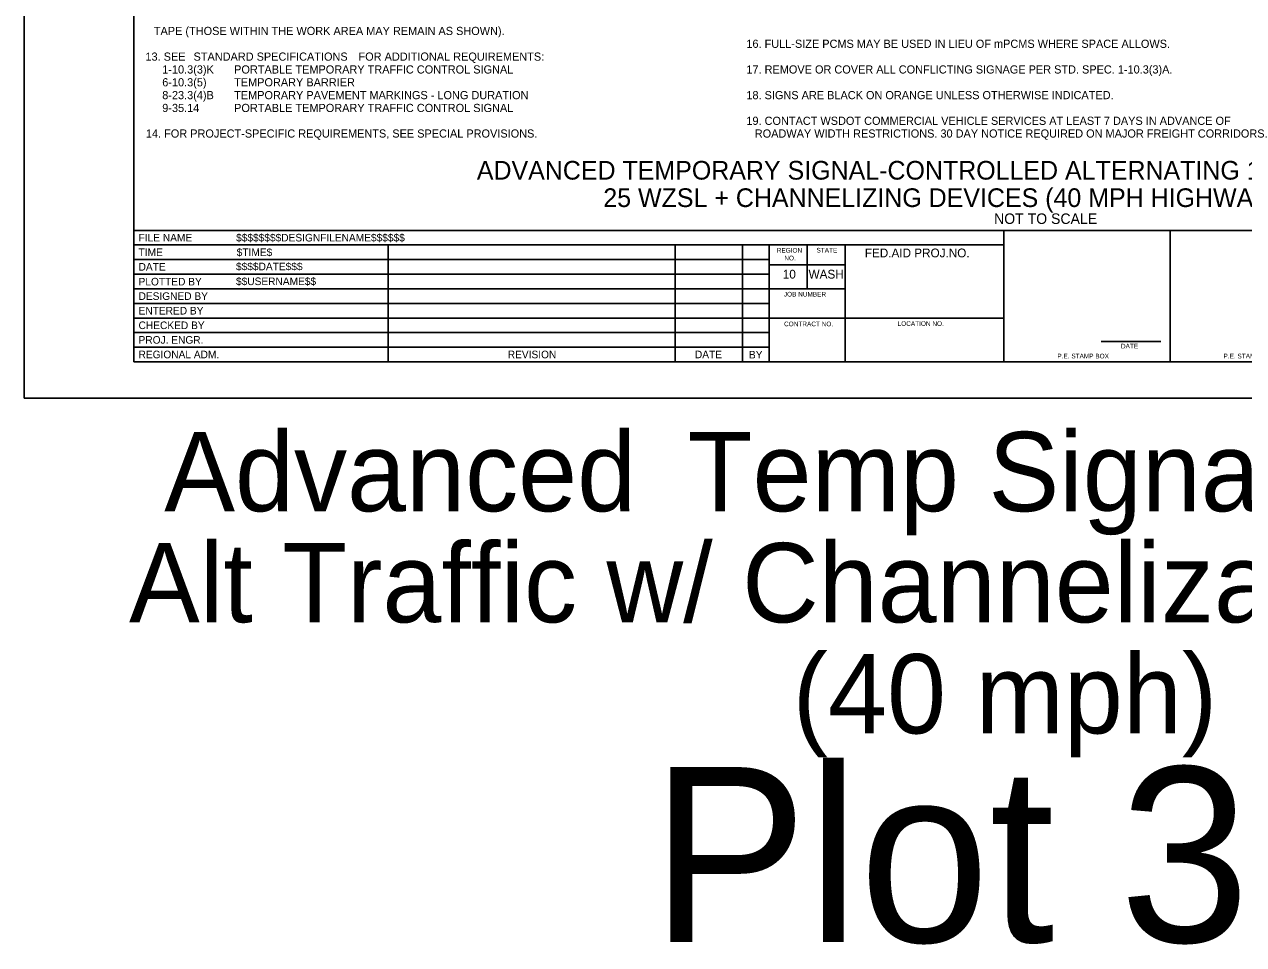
# Model space of a CAD drawing. Extents: x 99982 to 100176, y 99905 to 100011.
# Drawn here: x 100059.06 to 100069.51, y 99905.01 to 99912.89 of the extents above; entities that cross this region are included whole.
import ezdxf

# ---------------------------------------------------------------- set-up
doc = ezdxf.new("R2010")
doc.units = 0
for name, color, linetype in [('SH_DE_DetailHeading1Text', 7, 'Continuous'), ('SH_GI_GeneralNotesBodyText', 7, 'Continuous'), ('SH_GI_PlotLimits', 7, 'Continuous'), ('SH_GI_SheetBorder', 7, 'Continuous'), ('SH_GI_SheetLocationText', 7, 'Continuous'), ('SH_GI_SheetTextInCells', 7, 'Continuous'), ('SH_GI_TitleBlockText', 7, 'Continuous')]:
    doc.layers.add(name, color=color, linetype=linetype)

msp = doc.modelspace()

# ---------------------------------------------------------------- linework, layer by layer
at = {"layer": 'SH_GI_PlotLimits'}
msp.add_lwpolyline([(100059.062, 99909.687), (100076.062, 99909.687), (100076.062, 99920.687), (100059.062, 99920.687)], close=True, dxfattribs=at)
at = {"layer": 'SH_GI_SheetBorder'}
for p, q in [((100060, 99920.375), (100060, 99910)), ((100060, 99911.126), (100075.75, 99911.126)), ((100067.457, 99910), (100067.457, 99911.126)), ((100068.883, 99910), (100068.883, 99911.126)), ((100060, 99911.001), (100067.457, 99911.001)), ((100062.179, 99911.001), (100062.179, 99910)), ((100064.641, 99911.001), (100064.641, 99910)), ((100065.216, 99911.001), (100065.216, 99910)), ((100065.445, 99911.001), (100065.445, 99910)), ((100065.772, 99910.625), (100065.772, 99911.001)), ((100066.096, 99910), (100066.096, 99911.001)), ((100060, 99910.876), (100062.182, 99910.876)), ((100062.182, 99910.876), (100065.447, 99910.876)), ((100066.096, 99910.831), (100065.447, 99910.831)), ((100060, 99910.751), (100062.182, 99910.751)), ((100062.182, 99910.751), (100065.447, 99910.751)), ((100060, 99910.625), (100065.447, 99910.625)), ((100066.096, 99910.625), (100065.447, 99910.625)), ((100060, 99910.5), (100065.447, 99910.5)), ((100060, 99910.375), (100065.447, 99910.375)), ((100067.457, 99910.375), (100065.447, 99910.375)), ((100060, 99910.25), (100065.447, 99910.25)), ((100060, 99910.125), (100065.447, 99910.125)), ((100068.29, 99910.173), (100068.802, 99910.173)), ((100060, 99910), (100075.75, 99910))]:
    msp.add_line(p, q, dxfattribs=at)

# ---------------------------------------------------------------- texts
at = {"layer": 'SH_DE_DetailHeading1Text'}
for s, height, p in [('ADVANCED TEMPORARY SIGNAL-CONTROLLED ALTERNATING 1-LANE, 2-WAY TRAFFIC', 0.16, (100062.94, 99911.561)), ('25 WZSL + CHANNELIZING DEVICES (40 MPH HIGHWAYS, 8+ DAYS)', 0.16, (100064.024, 99911.326)), ('NOT TO SCALE', 0.09, (100067.373, 99911.181))]:
    msp.add_text(s, height=height, rotation=360, dxfattribs=at).set_placement(p)
at = {"layer": 'SH_GI_GeneralNotesBodyText'}
for s, p in [('TAPE (THOSE WITHIN THE WORK AREA MAY REMAIN AS SHOWN).', (100060.172, 99912.8)), ('16. FULL-SIZE PCMS MAY BE USED IN LIEU OF mPCMS WHERE SPACE ALLOWS.', (100065.25, 99912.69)), ('13. SEE ', (100060.1, 99912.58)), ('STANDARD SPECIFICATIONS', (100060.512, 99912.58)), (' FOR ADDITIONAL REQUIREMENTS:', (100061.9, 99912.58)), ('1-10.3(3)K', (100060.244, 99912.47)), ('PORTABLE TEMPORARY TRAFFIC CONTROL SIGNAL', (100060.86, 99912.47)), ('17. REMOVE OR COVER ALL CONFLICTING SIGNAGE PER STD. SPEC. 1-10.3(3)A. ', (100065.25, 99912.47)), ('6-10.3(5)', (100060.244, 99912.36)), ('TEMPORARY BARRIER', (100060.86, 99912.36)), ('8-23.3(4)B', (100060.244, 99912.25)), ('TEMPORARY PAVEMENT MARKINGS - LONG DURATION', (100060.86, 99912.25)), ('18. SIGNS ARE BLACK ON ORANGE UNLESS OTHERWISE INDICATED.', (100065.25, 99912.25)), ('9-35.14', (100060.244, 99912.14)), ('PORTABLE TEMPORARY TRAFFIC CONTROL SIGNAL', (100060.86, 99912.14)), ('19. CONTACT WSDOT COMMERCIAL VEHICLE SERVICES AT LEAST 7 DAYS IN ADVANCE OF ', (100065.25, 99912.03)), ('14. FOR PROJECT-SPECIFIC REQUIREMENTS, SEE SPECIAL PROVISIONS.', (100060.104, 99911.921)), ('ROADWAY WIDTH RESTRICTIONS. 30 DAY NOTICE REQUIRED ON MAJOR FREIGHT CORRIDORS.', (100065.322, 99911.921))]:
    msp.add_text(s, height=0.07, rotation=360, dxfattribs=at).set_placement(p)
at = {"layer": 'SH_GI_SheetLocationText'}
for s, height, p in [('Advanced', 0.68, (100060.261, 99908.719)), (' Temp Signal-Controlled', 0.68, (100064.495, 99908.719)), ('Alt Traffic w/ Channelization Devices', 0.68, (100059.959, 99907.767)), (' (40 mph)', 0.68, (100065.394, 99906.815)), ('Plot 34', 1.5, (100064.434, 99905.027))]:
    msp.add_text(s, height=height, dxfattribs=at).set_placement(p)
at = {"layer": 'SH_GI_SheetTextInCells'}
for s, height, p in [('FILE NAME', 0.0651, (100060.041, 99911.031)), ('TIME', 0.0651, (100060.041, 99910.906)), ('REGION', 0.04, (100065.51, 99910.935)), ('STATE', 0.04, (100065.851, 99910.936)), ('FED.AID PROJ.NO.', 0.07506, (100066.265, 99910.895)), ('NO.', 0.04, (100065.575, 99910.869)), ('DATE', 0.0651, (100060.041, 99910.781)), ('10', 0.0751, (100065.562, 99910.713)), ('WASH', 0.0751, (100065.783, 99910.713)), ('PLOTTED BY', 0.0651, (100060.041, 99910.654)), ('DESIGNED BY', 0.06505, (100060.041, 99910.53)), ('JOB NUMBER', 0.04, (100065.571, 99910.559)), ('ENTERED BY', 0.0651, (100060.041, 99910.405)), ('CHECKED BY', 0.0651, (100060.041, 99910.28)), ('CONTRACT NO.', 0.04003, (100065.573, 99910.304)), ('LOCATION NO.', 0.04003, (100066.546, 99910.307)), ('PROJ. ENGR.', 0.06505, (100060.041, 99910.155)), ('DATE', 0.04, (100068.46, 99910.114)), ('REGIONAL ADM.', 0.06505, (100060.041, 99910.03)), ('REVISION', 0.0651, (100063.205, 99910.03)), ('DATE', 0.0651, (100064.809, 99910.03)), ('BY', 0.0651, (100065.272, 99910.028)), ('P.E. STAMP BOX', 0.04003, (100067.915, 99910.029)), ('P.E. STAMP BOX', 0.04003, (100069.339, 99910.029))]:
    msp.add_text(s, height=height, dxfattribs=at).set_placement(p)
at = {"layer": 'SH_GI_TitleBlockText'}
for s, height, p in [('$$$$$$$$DESIGNFILENAME$$$$$$', 0.06505, (100060.877, 99911.031)), ('$TIME$', 0.0651, (100060.882, 99910.906)), ('$$$$DATE$$$', 0.06505, (100060.876, 99910.784)), ('$$USERNAME$$', 0.06505, (100060.876, 99910.657))]:
    msp.add_text(s, height=height, dxfattribs=at).set_placement(p)

doc.saveas('drawing.dxf')
